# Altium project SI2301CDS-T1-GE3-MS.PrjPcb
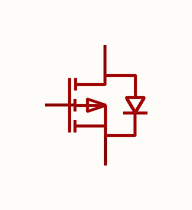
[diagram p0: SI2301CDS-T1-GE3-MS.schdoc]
1 sheet, 1 parts. Net scope: global (net labels, ports and power ports of the same name join across sheets).

## Sheet SI2301CDS-T1-GE3-MS.schdoc
size 127 x 101 mm

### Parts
Q?  si2301cds-t1-ge3-ms  [SOT-23-3_L2.9-W1.3-P1.90-LS2.4-BR]  (value not drawn)

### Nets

Not connected (* = marked no-connect by the designer): Q? 1(G) 2(S) 3(D)

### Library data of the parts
Q? = si2301cds-t1-ge3-ms: 数量:1个P沟道;漏源电压(Vdss):20V;连续漏极电流(Id):3A;导通电阻(RDS(on)):70mΩ@4.5V;耗散功率(Pd):1.56W;阈值电压(Vgs(th)):650mV;; Manufacturer: MSKSEMI(美森科); AddInBom: yes; ModelId: c62791f0466c4ae2a892c056b845b0ca; ModelName: SOT-23-3P_L2.9-W1.3-H1.0-LS2.4-P0.95; ModelTransform: 98.425,114.173,0,180,0,0,0.0005,-0.0005,0; Number: 1个P沟道; Drain to Source Voltage: 20V; Current - Continuous Drain(Id): 3A; Pd - Power Dissipation: 1.56W; Gate Threshold Voltage (Vgs(th)): 650mV; Gate Charge(Qg): 4.8nC@4.5V; Input Capacitance(Ciss): 550pF; Reverse Transfer Capacitance (Crss@Vds): 55pF; Type: P沟道; Output Capacitance(Coss): 65pF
